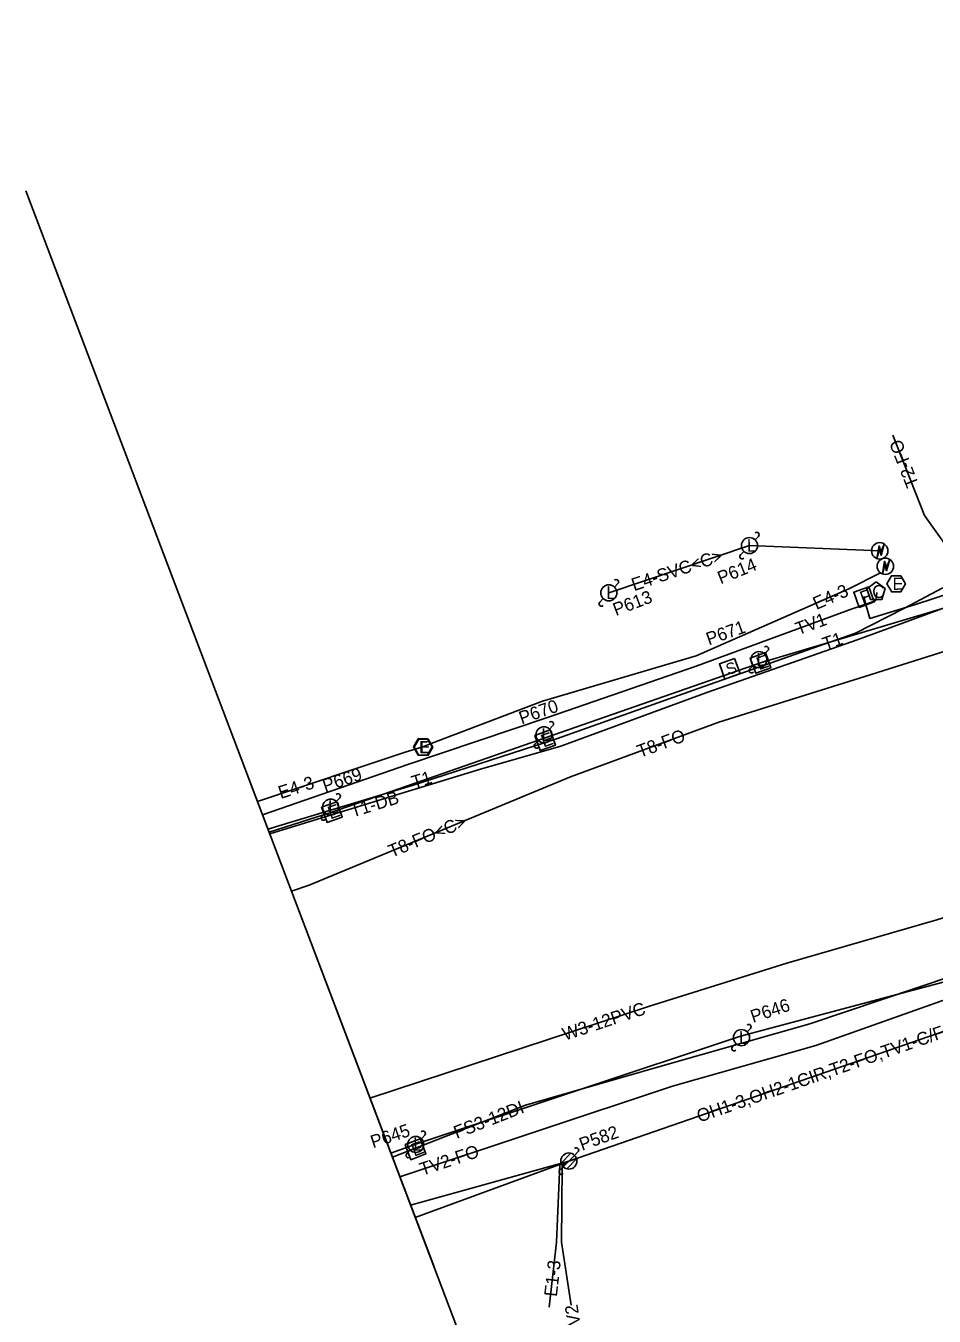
# Model space of a CAD drawing. Extents: x 2336688 to 2352634, y 362473 to 369571.
# Drawn here: x 2350002.6 to 2350284.9, y 368260.2 to 368661.2 of the extents above; entities that cross this region are included whole.
import ezdxf

# ---------------------------------------------------------------- set-up
doc = ezdxf.new("R2010")
doc.units = 0
for name, color, linetype in [('Default', 7, 'Continuous'), ('RD_EX_DV_Prop', 7, 'Continuous'), ('RD_EX_DV_TX_Prop', 7, 'Continuous'), ('RD_EX_RW', 7, 'Continuous'), ('RD_EX_RW_TX', 7, 'Continuous'), ('RD_HC_Data_Tic', 7, 'Continuous'), ('RD_PD_CstnLmt', 7, 'Continuous'), ('RD_PD_Final_TrvlWay', 7, 'Continuous'), ('RD_PD_PatLn4', 7, 'Continuous'), ('RD_SHT_ShtClip', 7, 'Continuous'), ('RD_Sketch1', 7, 'Continuous'), ('RD_Sketch2', 7, 'Continuous'), ('RD_Sketch5', 7, 'Continuous'), ('RD_Sketch8', 7, 'Continuous')]:
    doc.layers.add(name, color=color, linetype=linetype)

msp = doc.modelspace()

# ---------------------------------------------------------------- linework, layer by layer
at = {"layer": 'Default'}
for p, q in [((2350002.63, 368609.99), (2350212.93, 368055.44)), ((2350071.94, 368427.22), (2350129.48, 368275.51)), ((2350071.94, 368427.22), (2350129.48, 368275.51))]:
    msp.add_line(p, q, dxfattribs=at)
at = {"layer": 'RD_EX_RW_TX'}
for points in [[(2350171.87, 368427.87), (2350217.94, 368444.86), (2350264.95, 368459.5), (2350312.55, 368474.5), (2350359.96, 368486.74), (2350398.97, 368499.58), (2350441.96, 368515.14), (2350504.54, 368534.47), (2350552.41, 368547.56), (2350602.53, 368557.75), (2350651.32, 368575.57), (2350695.05, 368595.12), (2350743.66, 368609.85), (2350789.93, 368626.9), (2350839.13, 368641.87), (2350884.51, 368658.74), (2350931.21, 368675.96), (2350977.7, 368689.48), (2351026.67, 368705.73), (2351072.69, 368726.31)], [(2350078.43, 368410.11), (2350121.57, 368423.4), (2350143.91, 368430.19), (2350168.83, 368437.37), (2350214.23, 368453.99), (2350261.28, 368470.53), (2350307.48, 368487.5), (2350354.97, 368504.62), (2350408.06, 368522.73), (2350438.94, 368530.22), (2350481.48, 368544.67), (2350498.27, 368546.89), (2350550.8, 368551.91), (2350571.6, 368555.09), (2350599.59, 368561.91)], [(2350599.46, 368563.03), (2350571.6, 368556.05), (2350550.59, 368553.36), (2350498.04, 368549.07), (2350484.48, 368546.36), (2350482.64, 368545.94), (2350481.12, 368546.45), (2350467.8, 368557.82), (2350464.13, 368560.91), (2350460.65, 368560.51), (2350435.07, 368553), (2350413.22, 368546.93), (2350409.03, 368543.01), (2350408.48, 368537.37), (2350405.62, 368523.15), (2350399.7, 368520.91), (2350356.09, 368506.55), (2350306.59, 368490.37), (2350279.1, 368481.38), (2350264.89, 368477.05), (2350263.31, 368482.45), (2350263.08, 368483.91)], [(2350272, 368534.04), (2350281.85, 368509.07), (2350289.13, 368498.91), (2350293.42, 368495.17), (2350298.29, 368496.27), (2350346, 368513.18), (2350381.9, 368527.1), (2350394.9, 368530.89), (2350398.81, 368528.45), (2350399.92, 368528.37), (2350406.03, 368529.13), (2350404.87, 368530.3), (2350403.18, 368538.96), (2350401.8, 368540.99), (2350401.84, 368538.95), (2350400.7, 368528.92), (2350400.64, 368528.58), (2350399.92, 368528.37)], [(2350076.19, 368416.02), (2350121.33, 368431.67), (2350164.68, 368446.24), (2350210.89, 368462.22), (2350259.38, 368480.09), (2350266.63, 368482.56), (2350266.99, 368483.98), (2350267.09, 368485.14)], [(2350077.87, 368411.58), (2350122.65, 368425.12), (2350167.57, 368439.66), (2350213.31, 368455.95), (2350260.43, 368472.48), (2350275.43, 368480.16), (2350287.53, 368486.53)], [(2350577.9, 368452.25), (2350577.71, 368453.44), (2350574.65, 368455.11), (2350567.18, 368452.41), (2350530.66, 368434.99), (2350490.17, 368419.45), (2350440.7, 368401.32), (2350389.67, 368387.65), (2350345.03, 368375.16), (2350304.59, 368361.14), (2350291.95, 368359.89), (2350248.07, 368344.34), (2350203.54, 368331.65), (2350161.47, 368317.74), (2350118.87, 368303.47)], [(2350171.87, 368427.87), (2350090.67, 368394.19), (2350085.2, 368392.27)], [(2350171.37, 368308.42), (2350169.27, 368306.93), (2350169.05, 368283.25), (2350172.04, 368263.65)]]:
    msp.add_lwpolyline(points, dxfattribs=at)
for points in [[(2350266.81, 368488.4), (2350263.99, 368486.28), (2350265.12, 368482.95), (2350268.65, 368482.99), (2350269.69, 368486.36)], [(2350264.56, 368486.88), (2350259.87, 368485.17), (2350261.58, 368480.47), (2350266.27, 368482.18)]]:
    msp.add_lwpolyline(points, close=True, dxfattribs=at)
at = {"layer": 'RD_HC_Data_Tic'}
for p, q in [((2350229.23, 368501.49), (2350230.28, 368502.56)), ((2350224.68, 368496.84), (2350225.73, 368497.91)), ((2350185.54, 368486.8), (2350186.59, 368487.87)), ((2350180.99, 368482.16), (2350182.04, 368483.23)), ((2350232.16, 368466.01), (2350233.21, 368467.08)), ((2350227.62, 368461.37), (2350228.67, 368462.44)), ((2350165.38, 368442.67), (2350166.43, 368443.74)), ((2350160.83, 368438.03), (2350161.88, 368439.1)), ((2350099.11, 368420.21), (2350100.16, 368421.28)), ((2350094.56, 368415.57), (2350095.61, 368416.64)), ((2350226.75, 368348.55), (2350227.8, 368349.62)), ((2350222.2, 368343.91), (2350223.25, 368344.98)), ((2350125.54, 368315.36), (2350126.59, 368316.43)), ((2350120.99, 368310.72), (2350122.04, 368311.79)), ((2350168.96, 368307.78), (2350172.02, 368310.84)), ((2350173.14, 368310.19), (2350174.2, 368311.25)), ((2350168.54, 368305.59), (2350169.61, 368306.66)), ((2350169.61, 368306.66), (2350173.14, 368310.19)), ((2350170.73, 368306.01), (2350173.79, 368309.07))]:
    msp.add_line(p, q, dxfattribs=at)
for centre in [(2350227.48, 368499.7), (2350183.79, 368485.01), (2350230.42, 368464.23), (2350163.63, 368440.88), (2350097.36, 368418.42), (2350225, 368346.77), (2350123.79, 368313.58), (2350171.37, 368308.42)]:
    msp.add_circle(centre, 2.5, dxfattribs=at)
for centre, start, end in [((2350229.74, 368503.08), 315.5955, 135.5955), ((2350225.21, 368496.32), 135.5955, 315.5955), ((2350186.05, 368488.4), 315.5955, 135.5955), ((2350181.53, 368481.63), 135.5955, 315.5955), ((2350232.68, 368467.61), 315.5955, 135.5955), ((2350228.15, 368460.84), 135.5955, 315.5955), ((2350165.89, 368444.27), 315.5955, 135.5955), ((2350161.36, 368437.5), 135.5955, 315.5955), ((2350099.63, 368421.81), 315.5955, 135.5955), ((2350095.1, 368415.04), 135.5955, 315.5955), ((2350227.26, 368350.15), 315.5955, 135.5955), ((2350222.74, 368343.38), 135.5955, 315.5955), ((2350126.05, 368316.96), 315.5955, 135.5955), ((2350121.53, 368310.19), 135.5955, 315.5955), ((2350173.67, 368311.78), 315, 135), ((2350169.07, 368305.06), 135, 315)]:
    msp.add_arc(centre, 0.75, start, end, dxfattribs=at)
at = {"layer": 'RD_PD_Final_TrvlWay'}
msp.add_line((2350097.74, 368416.86), (2350078.23, 368410.63), dxfattribs=at)
for points in [[(2350097.74, 368416.86), (2350230.94, 368463.23), (2350297.22, 368483.05), (2350366.95, 368505.3)], [(2350183.79, 368485.01), (2350227.48, 368499.7), (2350267.97, 368498.06)], [(2350074.6, 368420.21), (2350120.49, 368435.45), (2350125.98, 368437.1), (2350128.61, 368438.15), (2350163.16, 368451.33), (2350210.91, 368465.41), (2350258.36, 368486.29), (2350268.15, 368491.27)], [(2350419.25, 368396.14), (2350416.48, 368398.17), (2350418.37, 368406.32), (2350330.49, 368375.37), (2350224.73, 368347.2), (2350123.83, 368313.64), (2350116.09, 368310.82)], [(2350171.37, 368308.42), (2350168.57, 368307.36), (2350167.5, 368283.25), (2350165.29, 368263.02)]]:
    msp.add_lwpolyline(points, dxfattribs=at)
for points in [[(2350269.33, 368500.13), (2350268.36, 368496.67), (2350267.85, 368498.54), (2350267.11, 368495.7), (2350267.76, 368499.62), (2350268.34, 368497.69)], [(2350271.06, 368495.34), (2350270.09, 368491.88), (2350269.58, 368493.75), (2350268.84, 368490.91), (2350269.49, 368494.83), (2350270.07, 368492.89)], [(2350275.97, 368487.85), (2350274.5, 368490.33), (2350271.62, 368490.3), (2350270.2, 368487.79), (2350271.67, 368485.3), (2350274.56, 368485.33)], [(2350232.46, 368466.42), (2350227.75, 368464.75), (2350229.41, 368460.04), (2350234.13, 368461.7)], [(2350128.87, 368437.1), (2350127.42, 368439.6), (2350124.54, 368439.6), (2350123.09, 368437.1), (2350124.54, 368434.6), (2350127.42, 368434.6)], [(2350129.07, 368437.06), (2350127.6, 368439.54), (2350124.71, 368439.51), (2350123.3, 368437), (2350124.77, 368434.51), (2350127.65, 368434.54)], [(2350165.52, 368442.39), (2350160.8, 368440.72), (2350162.47, 368436.01), (2350167.19, 368437.68)], [(2350099.26, 368420.05), (2350094.55, 368418.37), (2350096.22, 368413.66), (2350100.93, 368415.34)], [(2350125.19, 368315.28), (2350120.51, 368313.52), (2350122.28, 368308.84), (2350126.96, 368310.61)]]:
    msp.add_lwpolyline(points, close=True, dxfattribs=at)
for centre in [(2350267.97, 368498.06), (2350269.7, 368493.27)]:
    msp.add_circle(centre, 2.55, dxfattribs=at)
at = {"layer": 'RD_SHT_ShtClip'}
for p, q in [((2350171.37, 368308.42), (2350345.75, 368368.85)), ((2350122.19, 368294.72), (2350171.37, 368308.42)), ((2350123.63, 368290.92), (2350171.37, 368308.42))]:
    msp.add_line(p, q, dxfattribs=at)
at = {"layer": 'RD_Sketch2'}
msp.add_lwpolyline([(2351042.86, 368655.18), (2350995.25, 368636.19), (2350951.94, 368625.72), (2350904.41, 368609.66), (2350850.2, 368589.13), (2350807.88, 368571.45), (2350758.45, 368549.2), (2350717.62, 368531.89), (2350669.89, 368513.41), (2350618.71, 368497.66), (2350574.37, 368479.11), (2350524.2, 368457.7), (2350508, 368452.18), (2350504.2, 368450.53), (2350448.23, 368434.31), (2350382.35, 368413.96), (2350336.49, 368399.02), (2350285.67, 368383.39), (2350239.06, 368369.9), (2350196.44, 368356.53), (2350109.57, 368328)], dxfattribs=at)
at = {"layer": 'RD_Sketch5'}
msp.add_lwpolyline([(2350116.54, 368309.62), (2350157.85, 368325.74), (2350201.04, 368338.25), (2350246.21, 368351.09), (2350290.88, 368366.1), (2350342.68, 368382.19), (2350386.37, 368397.34), (2350435.33, 368415.03), (2350480.68, 368428.89), (2350526.02, 368446.27), (2350580.59, 368465.31), (2350628.33, 368480.35), (2350681.49, 368498.77), (2350722.35, 368517.44), (2350762.63, 368535.33), (2350810.28, 368554.98), (2350857.34, 368575.64), (2350905.94, 368596.06), (2350950.65, 368611.89), (2350997.52, 368629.24), (2351044.06, 368648.74)], dxfattribs=at)
at = {"layer": 'RD_Sketch8'}
msp.add_lwpolyline([(2350222.85, 368464.62), (2350218.15, 368462.91), (2350219.85, 368458.21), (2350224.55, 368459.92)], close=True, dxfattribs=at)

# ---------------------------------------------------------------- texts
at = {"layer": 'RD_EX_DV_Prop'}
for s, rotation, p in [('E4-SVC<C>', 18.6866, (2350191.62, 368485.5)), ('E4-3', 23.7469, (2350248.29, 368479.67)), ('E4-3', 17.8223, (2350081.83, 368420.92)), ('E1-3', 83.7506, (2350167.64, 368266.13))]:
    msp.add_text(s, height=4, rotation=rotation, dxfattribs=at).set_placement(p)
at = {"layer": 'RD_EX_DV_TX_Prop'}
for s, rotation, p in [('P614', 21.8821, (2350218.54, 368487.63)), ('P613', 20.5448, (2350185.97, 368477.79)), ('P671', 19.3428, (2350214.85, 368468.65)), ('P670', 19.3428, (2350156.69, 368444.09)), ('P669', 18.7705, (2350095.63, 368423.02)), ('P646', 18.3951, (2350228.58, 368351.31)), ('P645', 18.3951, (2350110.52, 368312.36)), ('P582', 19.8566, (2350175.46, 368311.59))]:
    msp.add_text(s, height=4, rotation=rotation, dxfattribs=at).set_placement(p)
at = {"layer": 'RD_EX_RW'}
for s, rotation, p in [('T2-FO', 111.5208, (2350280.2, 368518.7)), ('TV1', 20.2363, (2350242.65, 368471.79)), ('T1', 19.3275, (2350251.01, 368467.11)), ('T8-FO', 20.2412, (2350193.44, 368433.69)), ('T1', 17.1225, (2350123.21, 368424.11)), ('T1-DB', 17.1225, (2350104.18, 368415.16)), ('T8-FO<C>', 22.5267, (2350116.29, 368402.65)), ('TV2-FO', 18.319, (2350125.78, 368303.81)), ('TV2', 98.6741, (2350175.49, 368254.33))]:
    msp.add_text(s, height=4, rotation=rotation, dxfattribs=at).set_placement(p)
at = {"layer": 'RD_EX_RW_TX'}
for s, rotation, p in [('C', 0.7793, (2350265.65, 368483.38)), ('F', 20.0049, (2350262.69, 368481.41))]:
    msp.add_text(s, height=4, rotation=rotation, dxfattribs=at).set_placement(p)
at = {"layer": 'RD_HC_Data_Tic'}
for p in [(2350226.69, 368497.76), (2350183, 368483.07), (2350229.62, 368462.28), (2350162.84, 368438.94), (2350096.57, 368416.48), (2350224.21, 368344.82), (2350123, 368311.63)]:
    msp.add_text('L', height=4, rotation=0.5955, dxfattribs=at).set_placement(p)
at = {"layer": 'RD_PD_CstnLmt'}
msp.add_text('W3-12PVC', height=4, rotation=18.1813, dxfattribs=at).set_placement((2350170.16, 368345.8))
at = {"layer": 'RD_PD_Final_TrvlWay'}
for height, rotation, p in [(3.75, 0.5955, (2350271.97, 368485.93)), (4, 19.4719, (2350230.46, 368460.94)), (3.75, 0.5955, (2350125.07, 368435.14)), (4, 19.5025, (2350163.52, 368436.91)), (4, 19.5722, (2350097.27, 368414.56)), (4, 20.7124, (2350123.31, 368309.76))]:
    msp.add_text('E', height=height, rotation=rotation, dxfattribs=at).set_placement(p)
msp.add_text('E', height=3.75, dxfattribs=at).set_placement((2350124.84, 368435.22))
at = {"layer": 'RD_PD_PatLn4'}
msp.add_text('OH1-3,OH2-1CIR,T2-FO,TV1-C/FO,TF1,T4-FO', height=4, rotation=19.1115, dxfattribs=at).set_placement((2350211.93, 368320.36))
at = {"layer": 'RD_Sketch1'}
msp.add_text('FS3-12DI', height=4, rotation=21.3242, dxfattribs=at).set_placement((2350136.52, 368315.27))
at = {"layer": 'RD_Sketch8'}
msp.add_text('S', height=3.53, rotation=19.9352, dxfattribs=at).set_placement((2350220.93, 368459.38))

doc.saveas('drawing.dxf')
